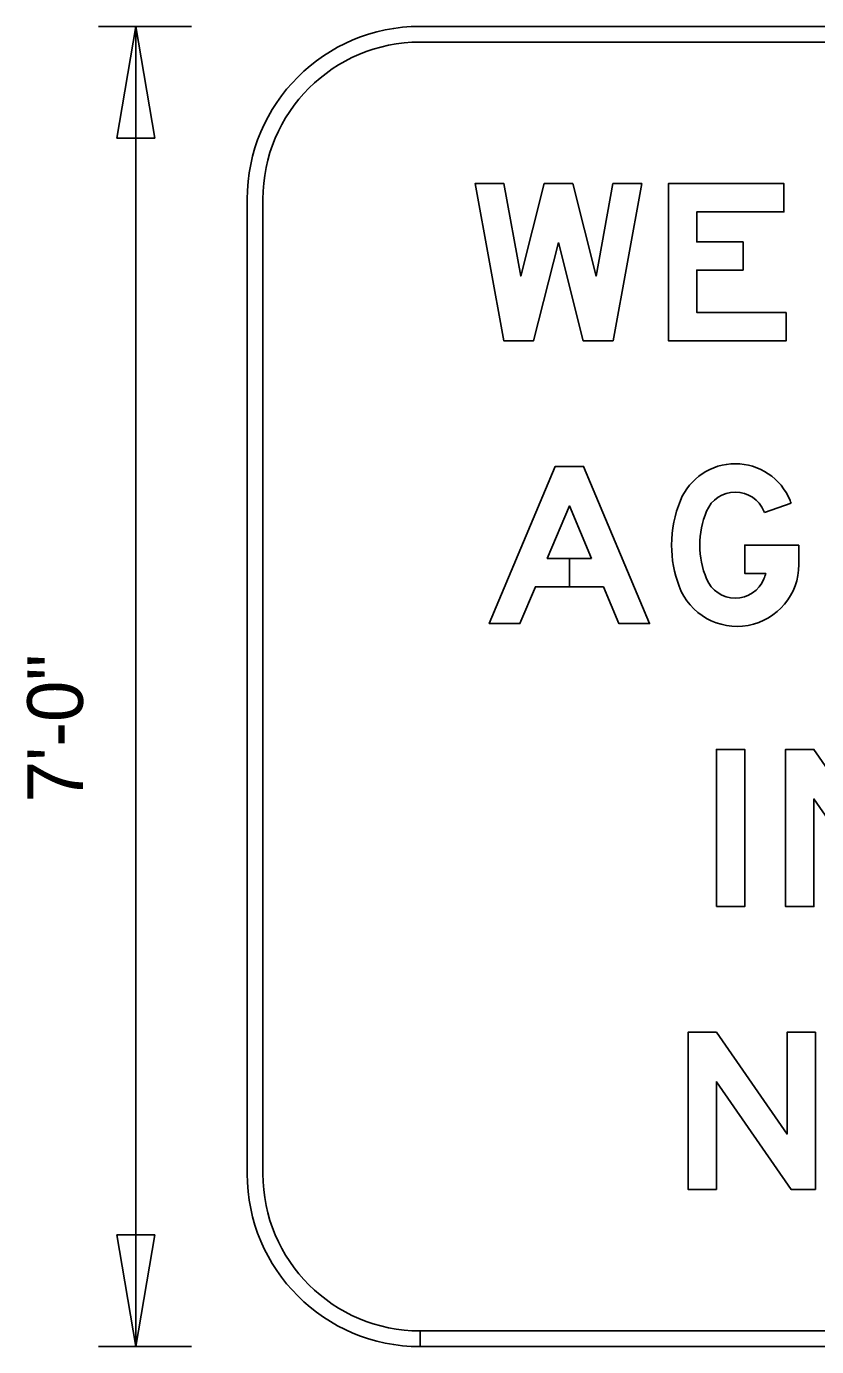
# Model space of a CAD drawing. Extents: x 0 to 770, y 0 to 495.
# Drawn here: x 584.1 to 633.7, y 218.8 to 301.8 of the extents above; entities that cross this region are included whole.
import ezdxf

# ---------------------------------------------------------------- set-up
doc = ezdxf.new("R2010")
doc.units = 0
for name, color, linetype in [('Dimension', 7, 'Continuous'), ('GSBWFill', 7, 'Continuous'), ('GSColorFill', 7, 'Continuous'), ('GSDims', 7, 'Continuous'), ('GSOutline', 7, 'Continuous'), ('TextStructures', 7, 'Continuous')]:
    doc.layers.add(name, color=color, linetype=linetype)

msp = doc.modelspace()

# ---------------------------------------------------------------- linework, layer by layer
at = {"layer": 'Dimension'}
for points in [[(590.947, 301.756), (589.758, 294.739), (592.136, 294.739)], [(590.947, 218.757), (592.136, 225.774), (589.758, 225.774)]]:
    msp.add_lwpolyline(points, close=True, dxfattribs=at)
at = {"layer": 'GSBWFill'}
for p, q in [((729.364, 301.756), (608.819, 301.756)), ((729.364, 301.756), (608.819, 301.756)), ((608.819, 300.768), (729.364, 300.768)), ((597.95, 290.887), (597.95, 229.626)), ((597.95, 290.887), (597.95, 229.626)), ((598.938, 229.626), (598.938, 290.887)), ((630.466, 271.193), (632.141, 271.793)), ((632.632, 267.927), (632.632, 269.149)), ((608.819, 218.757), (608.819, 219.746)), ((729.364, 219.746), (608.829, 219.746)), ((608.829, 219.746), (608.829, 218.757)), ((608.819, 218.757), (729.364, 218.757)), ((608.829, 218.757), (729.364, 218.757))]:
    msp.add_line(p, q, dxfattribs=at)
for points in [[(617.514, 288.17), (615.958, 281.994), (614.081, 281.994), (612.277, 291.875), (614.085, 291.875), (615.147, 286.056), (616.614, 291.875), (618.414, 291.875), (619.881, 286.056), (620.943, 291.875), (622.751, 291.875), (620.948, 281.994), (619.07, 281.994)], [(631.841, 283.773), (626.209, 283.773), (626.209, 286.431), (629.124, 286.431), (629.124, 288.209), (626.209, 288.209), (626.209, 290.097), (631.693, 290.097), (631.693, 291.875), (624.431, 291.875), (624.431, 281.994), (631.841, 281.994)], [(619.594, 268.31), (618.206, 268.31), (618.206, 266.531), (620.341, 266.531), (621.316, 264.209), (623.245, 264.209), (619.095, 274.09), (617.316, 274.09), (613.167, 264.209), (615.096, 264.209), (616.071, 266.531), (618.206, 266.531), (618.206, 268.31), (616.818, 268.31), (618.206, 271.614)], [(627.444, 246.424), (627.444, 256.304), (629.223, 256.304), (629.223, 246.424)], [(639.795, 256.304), (639.795, 246.424), (638.264, 246.424), (633.57, 253.192), (633.57, 246.424), (631.792, 246.424), (631.792, 256.304), (633.576, 256.304), (638.017, 249.901), (638.017, 256.304)], [(633.669, 238.519), (633.669, 228.638), (632.138, 228.638), (627.444, 235.407), (627.444, 228.638), (625.666, 228.638), (625.666, 238.519), (627.45, 238.519), (631.891, 232.116), (631.891, 238.519)]]:
    msp.add_lwpolyline(points, close=True, dxfattribs=at)
msp.add_lwpolyline([(632.632, 269.149), (629.223, 269.149), (629.223, 267.371), (630.562, 267.371)], dxfattribs=at)
for centre, radius, start, end in [((608.819, 290.887), 10.869, 90, 180), ((608.819, 290.887), 10.869, 90, 180), ((608.819, 290.887), 9.881, 90, 180), ((608.819, 229.626), 10.869, 180, 270), ((608.819, 229.626), 10.869, 180, 270), ((608.819, 229.626), 9.881, 180, 270)]:
    msp.add_arc(centre, radius, start, end, dxfattribs=at)
for centre, major_axis, start_param, end_param in [((628.63, 270.536), (0, 3.727), 5.10379, 7.46258), ((628.63, 270.536), (0, 1.948), 5.10379, 7.46258), ((631.989, 269.149), (0, 7.361), 1.179395, 1.570796), ((625.27, 269.149), (0, 7.361), 5.07965, 5.10379), ((631.989, 269.149), (0, 5.583), 1.179395, 1.570796), ((625.27, 269.149), (0, 5.583), 5.087148, 5.10379), ((631.989, 269.149), (0, 7.361), 1.570796, 1.930863), ((631.989, 269.149), (0, 5.583), 1.570796, 1.962198), ((628.741, 267.927), (0, 3.89), 1.930863, 4.712389), ((625.27, 269.149), (0, 5.583), 4.320988, 4.388154), ((628.63, 267.763), (0, 1.948), 1.962198, 4.320988)]:
    msp.add_ellipse(centre, major_axis=major_axis, ratio=0.999994, start_param=start_param, end_param=end_param, dxfattribs=at)
at = {"layer": 'GSColorFill'}
for p, q in [((630.466, 271.193), (632.141, 271.793)), ((632.632, 267.927), (632.632, 269.149))]:
    msp.add_line(p, q, dxfattribs=at)
for points in [[(617.514, 288.17), (615.958, 281.994), (614.081, 281.994), (612.277, 291.875), (614.085, 291.875), (615.147, 286.056), (616.614, 291.875), (618.414, 291.875), (619.881, 286.056), (620.943, 291.875), (622.751, 291.875), (620.948, 281.994), (619.07, 281.994)], [(631.841, 283.773), (626.209, 283.773), (626.209, 286.431), (629.124, 286.431), (629.124, 288.209), (626.209, 288.209), (626.209, 290.097), (631.693, 290.097), (631.693, 291.875), (624.431, 291.875), (624.431, 281.994), (631.841, 281.994)], [(619.594, 268.31), (618.206, 268.31), (618.206, 266.531), (620.341, 266.531), (621.316, 264.209), (623.245, 264.209), (619.095, 274.09), (617.316, 274.09), (613.167, 264.209), (615.096, 264.209), (616.071, 266.531), (618.206, 266.531), (618.206, 268.31), (616.818, 268.31), (618.206, 271.614)], [(627.444, 246.424), (627.444, 256.304), (629.223, 256.304), (629.223, 246.424)], [(639.795, 256.304), (639.795, 246.424), (638.264, 246.424), (633.57, 253.192), (633.57, 246.424), (631.792, 246.424), (631.792, 256.304), (633.576, 256.304), (638.017, 249.901), (638.017, 256.304)], [(633.669, 238.519), (633.669, 228.638), (632.138, 228.638), (627.444, 235.407), (627.444, 228.638), (625.666, 228.638), (625.666, 238.519), (627.45, 238.519), (631.891, 232.116), (631.891, 238.519)]]:
    msp.add_lwpolyline(points, close=True, dxfattribs=at)
msp.add_lwpolyline([(632.632, 269.149), (629.223, 269.149), (629.223, 267.371), (630.562, 267.371)], dxfattribs=at)
for centre, major_axis, start_param, end_param in [((628.63, 270.536), (0, 3.727), 5.10379, 7.46258), ((628.63, 270.536), (0, 1.948), 5.10379, 7.46258), ((631.989, 269.149), (0, 7.361), 1.179395, 1.570796), ((625.27, 269.149), (0, 7.361), 5.07965, 5.10379), ((631.989, 269.149), (0, 5.583), 1.179395, 1.570796), ((625.27, 269.149), (0, 5.583), 5.087148, 5.10379), ((631.989, 269.149), (0, 7.361), 1.570796, 1.930863), ((631.989, 269.149), (0, 5.583), 1.570796, 1.962198), ((628.741, 267.927), (0, 3.89), 1.930863, 4.712389), ((625.27, 269.149), (0, 5.583), 4.320988, 4.388154), ((628.63, 267.763), (0, 1.948), 1.962198, 4.320988)]:
    msp.add_ellipse(centre, major_axis=major_axis, ratio=0.999994, start_param=start_param, end_param=end_param, dxfattribs=at)
at = {"layer": 'GSDims'}
for p, q in [((594.449, 301.756), (588.613, 301.756)), ((590.947, 218.757), (590.947, 301.756)), ((594.449, 218.757), (588.613, 218.757))]:
    msp.add_line(p, q, dxfattribs=at)
at = {"layer": 'GSOutline'}
for p, q in [((630.466, 271.193), (632.141, 271.793)), ((632.632, 267.927), (632.632, 269.149))]:
    msp.add_line(p, q, dxfattribs=at)
for points in [[(617.514, 288.17), (615.958, 281.994), (614.081, 281.994), (612.277, 291.875), (614.085, 291.875), (615.147, 286.056), (616.614, 291.875), (618.414, 291.875), (619.881, 286.056), (620.943, 291.875), (622.751, 291.875), (620.948, 281.994), (619.07, 281.994)], [(631.841, 283.773), (626.209, 283.773), (626.209, 286.431), (629.124, 286.431), (629.124, 288.209), (626.209, 288.209), (626.209, 290.097), (631.693, 290.097), (631.693, 291.875), (624.431, 291.875), (624.431, 281.994), (631.841, 281.994)], [(616.071, 266.531), (620.341, 266.531), (621.316, 264.209), (623.245, 264.209), (619.095, 274.09), (617.316, 274.09), (613.167, 264.209), (615.096, 264.209)], [(619.594, 268.31), (618.206, 271.614), (616.818, 268.31)], [(627.444, 246.424), (627.444, 256.304), (629.223, 256.304), (629.223, 246.424)], [(639.795, 256.304), (639.795, 246.424), (638.264, 246.424), (633.57, 253.192), (633.57, 246.424), (631.792, 246.424), (631.792, 256.304), (633.576, 256.304), (638.017, 249.901), (638.017, 256.304)], [(633.669, 238.519), (633.669, 228.638), (632.138, 228.638), (627.444, 235.407), (627.444, 228.638), (625.666, 228.638), (625.666, 238.519), (627.45, 238.519), (631.891, 232.116), (631.891, 238.519)]]:
    msp.add_lwpolyline(points, close=True, dxfattribs=at)
msp.add_lwpolyline([(632.632, 269.149), (629.223, 269.149), (629.223, 267.371), (630.562, 267.371)], dxfattribs=at)
for centre, major_axis, start_param, end_param in [((628.63, 270.536), (0, 3.727), 5.10379, 7.46258), ((628.63, 270.536), (0, 1.948), 5.10379, 7.46258), ((631.989, 269.149), (0, 7.361), 1.179395, 1.570796), ((625.27, 269.149), (0, 7.361), 5.07965, 5.10379), ((631.989, 269.149), (0, 5.583), 1.179395, 1.570796), ((625.27, 269.149), (0, 5.583), 5.087148, 5.10379), ((631.989, 269.149), (0, 7.361), 1.570796, 1.930863), ((631.989, 269.149), (0, 5.583), 1.570796, 1.962198), ((628.741, 267.927), (0, 3.89), 1.930863, 4.712389), ((625.27, 269.149), (0, 5.583), 4.320988, 4.388154), ((628.63, 267.763), (0, 1.948), 1.962198, 4.320988)]:
    msp.add_ellipse(centre, major_axis=major_axis, ratio=0.999994, start_param=start_param, end_param=end_param, dxfattribs=at)

# ---------------------------------------------------------------- texts
at = {"layer": 'TextStructures'}
msp.add_text('7\'-0"', height=3.5, rotation=90, dxfattribs=at).set_placement((587.626, 252.97))

doc.saveas('drawing.dxf')
